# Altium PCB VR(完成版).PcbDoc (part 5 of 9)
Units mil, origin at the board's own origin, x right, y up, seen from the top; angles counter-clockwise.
Board outline 2839.68 x 2020.7 mil, 6 copper layers (TOP, GND02, SIN03, SIN04, PWR05, BOTTOM); 494 components, 404 nets, 7124 pads, 1123 vias.
Unrouted connection lines stored in the file: 10.
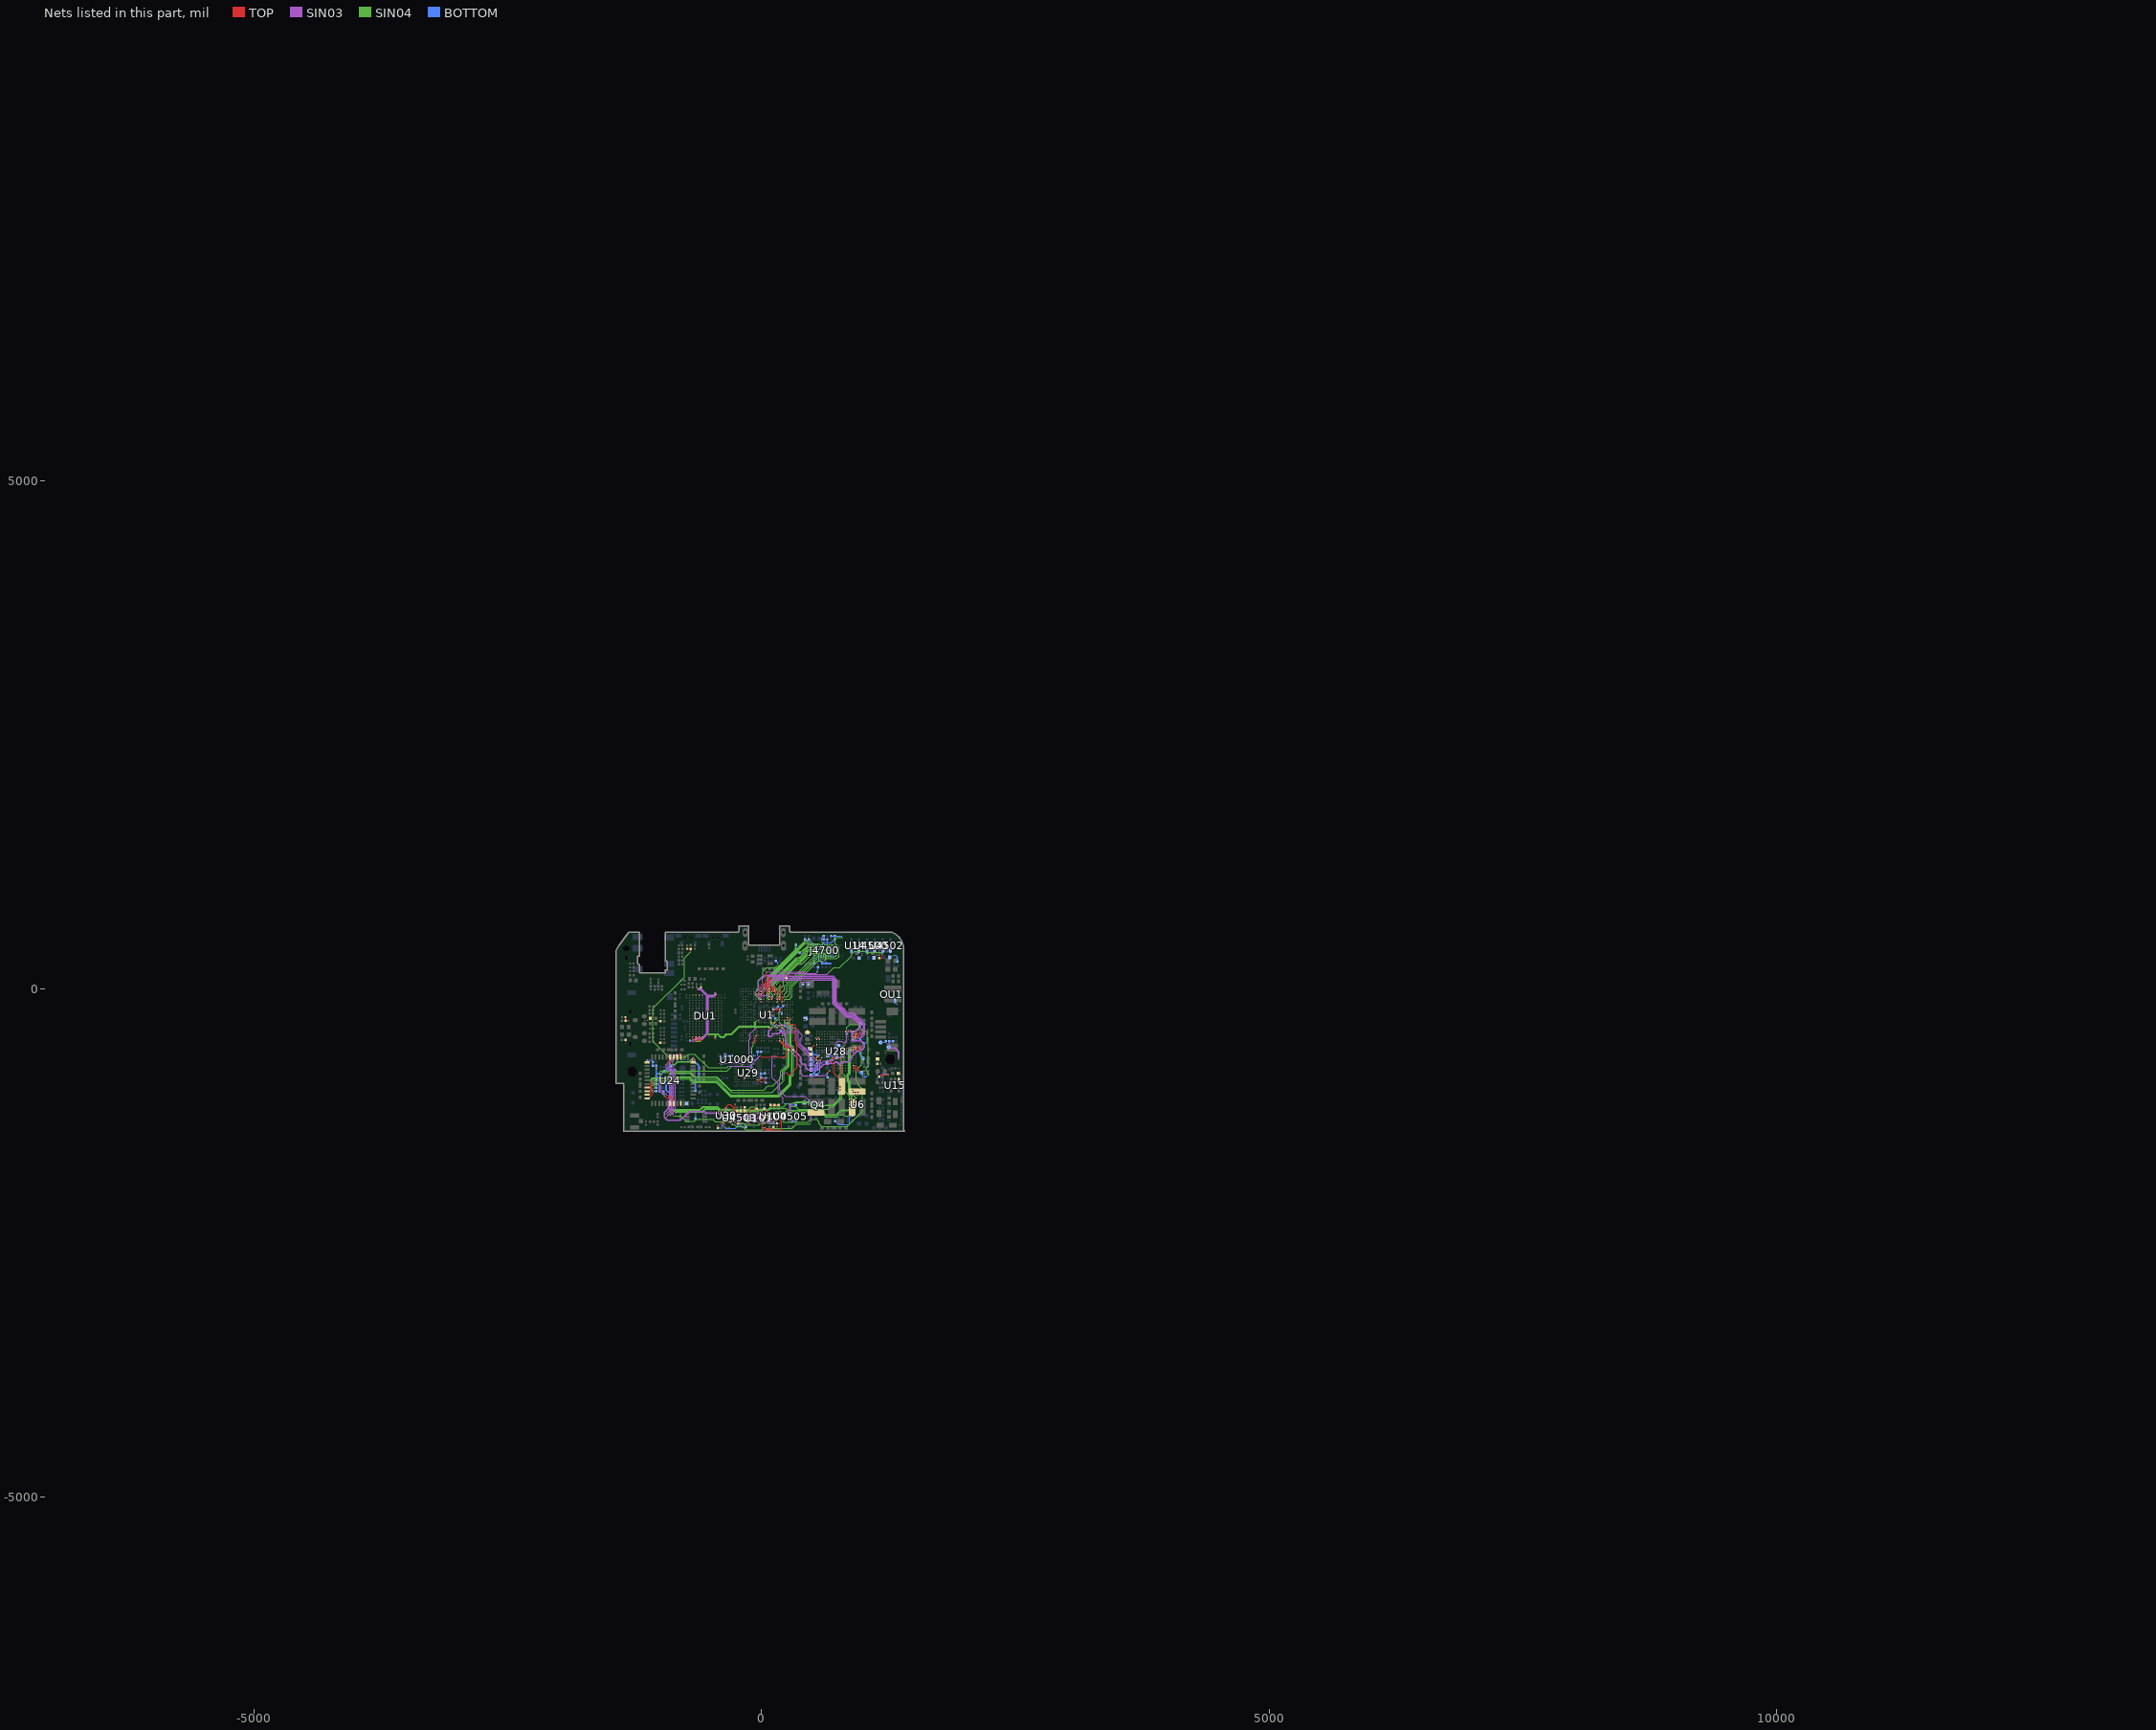
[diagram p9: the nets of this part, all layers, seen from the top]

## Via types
v1: diameter 14, hole 8, TOP to BOTTOM, tented both sides, 707 vias
v2: diameter 16, hole 10, TOP to BOTTOM, tented both sides, 275 vias
v3: diameter 16, hole 8, TOP to BOTTOM, tented both sides, 134 vias
v4: diameter 8, hole 8, TOP to BOTTOM, tented both sides, 3 vias
v5: diameter 10, hole 10, TOP to BOTTOM, tented both sides, 2 vias
v6: diameter 14, hole 8, TOP to BOTTOM, tented top, 1 vias
v7: diameter 14, hole 10, TOP to BOTTOM, tented both sides, 1 vias

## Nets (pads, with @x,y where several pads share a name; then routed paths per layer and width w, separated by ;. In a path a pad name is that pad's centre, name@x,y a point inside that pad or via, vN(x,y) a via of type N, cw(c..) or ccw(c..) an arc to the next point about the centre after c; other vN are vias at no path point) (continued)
ALDO2: C5.2 C6.2 C7.1 C76.2 C197.1 C230.2 DC1.2 DC22.2 DC23.2 DU1.A3 DU1.A4 DU1.A5 DU1.A6 DU1.A10 DU1.U3 DU1.U4 DU1.U5 DU1.U6 DU1.U10 U1.N8 U1.T12 U1.T13 U28.H2 U28.T4 | length 4187.4
  TOP w4: DU1.A6@-582.97,-58.91 DU1.A6@-580.5,-61.38
  TOP w10: -674.99,-495.43 DU1.U3@-674.99,-471.75 -674.99,-504.14 v3(-667.27,-511.86) -648.86,-511.86 -643.49,-506.49 ; DU1.U4@-643.49,-471.75 -643.49,-506.49 ; DU1.U5@-612,-471.75 -612,-501 ; DU1.U6@-580.5,-471.75 -580.5,-498.5 -583,-501 -612,-501 ; DU1.A6@-580.5,-62.3 DU1.A6@-580.5,-61.38 ; v1(-454.52,-489.45) DU1.U10@-454.52,-471.75 ; DU1.A10@-454.52,-62.3 v1@-454.52,-47.66 ; v1(-38.39,-319.89) U1.N8@-25.59,-307.09 ; U1.T12@76.77,-383.86 v1(89.57,-396.65) U1.T13@102.36,-383.86 ; U28.H2@904.95,-625.83 v3(917.75,-638.63) ; -643.49,-506.49 -617.49,-506.49 -612,-501
  TOP w12: U28.T4@853.77,-421.1 v3(866.56,-408.31)
  SIN03 w12: v1(89.57,-396.65) 71,-415.22 71,-463 77,-469 94,-469 120,-443 171,-443 186,-428 200,-428 237,-465 237,-525 386,-674 386,-722 405.81,-741.81 425.81,-741.81 439,-755 439,-775 463,-799 557,-799 613,-743 659,-743 670,-732 717,-732 732,-717 740,-717 765,-742 777,-742 801,-718 854,-718 887,-685 887,-669.37 v3(917.75,-638.63) 952.37,-604 985,-604 1014,-575 1014,-547 980,-513 898,-513 890,-505 890,-431.74 v3(866.56,-408.31)
  SIN03 w25: v3(-667.27,-511.86) -643.64,-488.22 -582.78,-488.22 -533.08,-438.53 -533.08,-71 -470,-71 -453.88,-54.88 v1(-453.88,-43.41) ; v3(-617.59,-3.54) -596.06,-3.54 -533.08,-66.53
  SIN04 w15: -62,-371 -62,-330 -51.89,-319.89 v1(-38.39,-319.89)
  SIN04 w20: v3(-667.27,-511.86) -606.41,-511.86 -544.08,-449.53 -454.52,-449.53 ; v1(-454.52,-489.45) -454.52,-449.53 ; v1@88.5,-390.5 69,-371 -62,-371 -218,-371 -295.53,-448.53 -344.58,-448.53 -373.08,-477.03 -396.58,-477.03 -424.08,-449.53 -454.52,-449.53
  BOTTOM w5: v3(866.56,-408.31) v3@874.18,-408.31 ; C230.2@890.28,-424.41 C230.2@890.41,-424.41
  BOTTOM w8: v3(917.75,-638.63) 935.52,-620.86 962.96,-620.86 C197.1@975.96,-633.86
  BOTTOM w10: DC1.2@-704.3,-510.42 -702.86,-511.86 v3(-667.27,-511.86)
  BOTTOM w12: C5.2@68,-458 C7.1@68,-418 68.22,-418 v1(89.57,-396.65) ; C230.2@890.41,-424.41 888.41,-424.41 887,-423 923,-423 971,-375 971,-347.65 C76.2@977.41,-341.24 ; C197.1@975.96,-633.86 975.96,-657.96 C6.2@1003,-685
  BOTTOM w15: v3(-667.27,-511.86) -632.63,-511.86 DC22.2@-631.19,-510.42 ; v3@874.18,-408.31 C230.2@890.28,-424.41
ALDO3: C11.2 C78.2 C227.2 R162.2 U1.T15 U28.C2 U28.T5 | length 2484
  TOP w5: 917.75,-766.58 917.75,-786.75 923.16,-792.16 951.73,-792.16
  TOP w5.5: 917.75,-766.58 941.58,-766.58 951.73,-776.73
  TOP w10: U1.T15@153.54,-383.86 v1(166.33,-396.66) ; U28.T5@828.18,-421.1 v3(840.98,-408.31) ; U28.C2@904.95,-753.78 917.75,-766.58
  TOP w15: v3(951.73,-823) 951.73,-776.73
  SIN03 w10: v1(166.33,-396.66) 195.66,-396.66 229,-430 330,-430 344,-444 344,-544 469,-669 469,-757 486,-774 548,-774 614,-708 701,-708 732,-677 732,-536 754,-514 792,-514 807,-529 826,-529 840.98,-514.02 v3(840.98,-408.31)
  SIN04 w10: v3(840.98,-408.31) 840.98,-380.02 872,-349 960,-349 971.31,-360.31 971.31,-386.31 997,-412 1026,-412 1041,-427 1041,-468 1053,-480 1053,-759.73 1033,-779.73 1033,-806.5 1053,-826.5 1053,-857.5 1044.5,-866 v1@1045,-866
  BOTTOM w5: C78.2@985,-820.06 C78.2@986.94,-822
  BOTTOM w10: v1(166.33,-396.66) 178.66,-396.66 C11.2@192,-410 ; C227.2@840.98,-443.34 v3(840.98,-408.31) ; v3(951.73,-823) 954.67,-820.06 C78.2@985,-820.06 ; C78.2@986.94,-822 986.94,-847.94 1004,-865 ; R162.2@1006.79,-532.86 1028.14,-532.86 1041,-520 v1@1041,-468
  BOTTOM w12: 1004,-865 v1(1045,-865)
  other v1: 1043,-468
AP-CK32K1: R188.1 R196.1 R464.1 | length 70.8
  BOTTOM w5: R464.1@-888.27,-832.48 R188.1@-888.27,-796.86 -853.65,-796.86 R196.1@-853.27,-797.24
AP-CK32KO: R464.2 R465.2 U28.C7 | length 2755.4
  TOP w5: U28.C7@777,-753.78 789.8,-766.58 v3(789.8,-861.93)
  SIN03 w4: v1(-944,-855) -902,-897 -902,-1199 v1(-935,-1232)
  SIN04 w4: v1@-935,-1233 -888,-1186 -788,-1186 ; -804,-1186 -788,-1186 ; v3(789.8,-861.93) 813,-885.14 813,-1027 793,-1047 793,-1080 709.84,-1163.16 680.84,-1163.16 660,-1184 362,-1184 334,-1156 295,-1156 267,-1128 250,-1128 217,-1161 91,-1161 68,-1184 -32,-1184 -52,-1164 -103,-1164 -123,-1184 -402,-1184 -430,-1156 -574,-1156 -604,-1186 -788,-1186
  BOTTOM w5: v1(-944,-855) -931.14,-867.86 R464.2@-888.27,-867.86 ; R464.2@-894.13,-862 R464.2@-888.27,-867.86 ; R465.2@-853.27,-867.86 R464.2@-888.27,-867.86
AP-CSI-SCK: J4700.6 R4700.2 U1.C12 | length 836.8
  TOP w5: v1(45,80) 45,11 64,-8 64,-38.42 U1.C12@76.77,-51.19
  SIN04 w4: v1(45,80) 45,85 436,476 479,476 v1@494,461
  BOTTOM w5: R4700.2@468.73,486.14 v1(493.87,461) 505.51,449.36 J4700.6@505.51,431.14
AP-CSI-SDA: J4700.4 R4701.2 U1.B13 | length 764.1
  TOP w5: v1(91,105.39) 91,34 116,9 116,-11.95 U1.B13@102.36,-25.59
  SIN04 w4: v1(91,105.39) 91,118 430,457 v1(471,457)
  BOTTOM w5: R4701.2@429.37,486.14 452.37,463.14 464.86,463.14 481.89,446.11 J4700.4@481.89,431.14
AP-I2S-BCLK: U1.A10 U28.R2 | length 1779.7
  TOP w5: v1(12.79,63.99) 25.59,51.19 U1.A10@25.59,0 ; U28.R2@904.95,-446.69 917.75,-433.89 937,-433.89 941,-429.89 v1(951.34,-429.89)
  SIN03 w4: v1(12.79,63.99) 12.79,99.79 40,127 503,127 ; 520,127 503,127 ; v1(951.34,-429.89) 929,-452.23 929,-468 947,-486 982,-486 1019,-449 1019,-346 913,-240 855,-240 741,-126 741,92 706,127 503,127
AP-I2S-DIN: U1.B9 U28.P2 | length 1687.5
  TOP w4: -12.8,-12.8 U1.B9@0,-25.59
  TOP w5: -12.8,-12.8 v1(-12.8,38.39) ; U28.P2@904.95,-472.28 917.75,-459.48 v3(943.34,-459.48)
  SIN03 w4: v1(-12.8,38.39) 28.39,38.39 65,75 65,109 75,119 699,119 731.87,86.13 731.87,-132.87 847,-248 905,-248 1011,-354 1011,-439 976,-474 957.85,-474 v3(943.34,-459.48)
AP-I2S-DOUT0: U1.E9 U28.P1 | length 1689.3
  TOP w4: -12.8,-89.57 U1.E9@0,-102.37
  TOP w5: -12.8,-89.57 v1(-12.8,-38.39) ; U28.P1@930.54,-472.28 933.26,-475 953.41,-475 v3(968.93,-459.48)
  SIN03 w4: v1(-12.8,-38.39) -12.8,2.2 5,20 34,20 122,108 478,108 ; 515,108 478,108 ; v3(968.93,-459.48) 1003,-425.41 1003,-358 905,-260 846,-260 722.68,-136.68 722.68,82.32 697,108 478,108
AP-I2S-LRCK: U1.C9 U28.R1 | length 1502.9
  TOP w5: U1.C9@0,-51.19 12.8,-38.39 v1(12.8,-12.79) ; U28.R1@930.54,-446.69 932.23,-445 961.82,-445 v1@976.93,-429.89
  SIN03 w4: v1(12.8,-12.79) 35.59,10 45,10 134,99 693,99 713.49,78.51 713.49,-140.49 842,-269 898,-269 976.93,-347.93 v1@976.93,-429.89
  other v1: 973.93,-429.89
AP-I2S-MCLK: U1.C8 U28.T2 | length 1535.3
  TOP w4: v1(-38.39,-38.39) U1.C8@-25.59,-51.19
  TOP w5: U28.T2@904.95,-421.1 917.75,-408.31 v1(963.93,-408.31)
  SIN03 w4: v1(-38.39,-38.39) -20.78,-56 -3,-56 141,88 373,88 394,67 492,67 513,88 583,88 688,88 705,71 705,-144 840,-279 894,-279 963.93,-348.93 v1(963.93,-408.31)
AP-NMI#: C280.2 R33.2 U1.Y16 U28.A11 | length 975.4
  TOP w4: U1.Y16@179.13,-486.23 v1(191.93,-499.02)
  TOP w5: v1(191.93,-499.02) 191.93,-510.93 255,-574 288,-574 C280.2@314,-600 ; v3(661.83,-817.76) U28.A11@674.63,-804.96
  SIN03 w4: v1(191.93,-499.02) 191.93,-519.93 355.5,-683.5 355.5,-741.5 386,-772 386,-834 406,-854 625.59,-854 v3(661.83,-817.76)
  BOTTOM w5: R33.2@650.41,-866.86 650.41,-829.18 v3(661.83,-817.76)
AP-RESET#: C79.2 C277.1 R17.2 R93.1 R1006.1 U1.AA16 | length 3580.4
  TOP w4: U1.AA16@179.13,-511.82 191.93,-524.61
  TOP w5: v1(-15,-659) 0,-674 85,-674 98,-661 v1(145,-661) 156,-672 230,-672 246,-656 246,-621 C277.1@268,-599 266.32,-599 191.93,-524.61
  TOP w10: C79.2@-730.27,396.69 -696.82,396.69 R17.2@-694.27,394.14 v1(-694.27,366.14)
  SIN03 w4: v1(-323,-760) -116,-760 v1(-15,-659) ; v1(145,-661) 116,-661 105,-672 105,-874 167,-936 167,-1028 214,-1075 v2(214,-1130)
  SIN04 w4: v1(-694.27,366.14) -759,301.41 -759,116 -1068,-193 -1068,-515 -913,-670 -746.89,-670 -718.89,-642 -656.11,-642 -523.11,-775 -338,-775 v1(-323,-760)
  BOTTOM w5: R1006.1@-86.89,-693.25 -49.25,-693.25 v1(-15,-659) ; v2(214,-1130) 284,-1130 297.24,-1143.24 317,-1143.24 ; 310.11,-1143.24 317,-1143.24 ; R93.1@340.41,-1143.24 317,-1143.24
AP-UART1-CTS: R179.2 U1.N19 U24.41 | length 2292.6
  TOP w4: v1(243.1,-319.89) U1.N19@255.9,-307.09
  TOP w5: U24.41@-1126.27,-971.56 -1108.56,-971.56 -1089,-952 -1089,-926 v2(-1064,-901)
  SIN04 w4: v2(-1064,-901) -931,-901 -904,-874 -711,-874 -674,-911 -444,-911 -302.5,-1052.5 170.5,-1052.5 285,-938 285,-862 305,-842 305,-575 283,-553 283,-422 292,-413 292,-368.78 v1(243.1,-319.89)
  BOTTOM w5: v2(-1064,-901) -1037.39,-901 R179.2@-1037.27,-901.12
AP-UART1-RTS: R182.2 U1.N18 U24.44 | length 2479
  TOP w4: v1(217.51,-319.89) U1.N18@230.31,-307.09
  TOP w5: U24.44@-1126.27,-1077.86 -1109.86,-1077.86 -1066,-1034 v2(-1066,-1008)
  SIN04 w4: v2(-1066,-1008) -1085,-989 -1085,-959 -1078,-952 -1053,-952 -1047.65,-946.65 -1047.65,-929.35 -1060,-917 -1073,-917 -1080,-910 -1080,-893 -1073,-886 -929,-886 -906,-863 -706,-863 -669,-900 -442,-900 -299.92,-1042.08 167.92,-1042.08 273,-937 273,-858 296,-835 296,-585 272,-561 272,-419 282,-409 282,-374 245.19,-337.19 234.81,-337.19 v1(217.51,-319.89)
  BOTTOM w5: v2@-1063,-1008 -1037.41,-1008 R182.2@-1037.27,-1007.86
AP-UART1-RX: R180.2 U1.N16 U24.42 | length 2350.1
  TOP w4: v1(166.33,-319.89) U1.N16@179.13,-307.09
  TOP w5: U24.42@-1126.27,-1006.99 -1109.99,-1006.99 -1089,-986 -1089,-969 -1076,-956 -1076,-947 v2(-1066,-937) -1066,-940 v2@-1063,-937
  SIN04 w4: v2(-1066,-937) -1088,-915 -1088,-888 -1075,-875 -937,-875 -894,-832 -702,-832 -654.5,-879.5 -435.5,-879.5 -293,-1022 107,-1022 224,-905 224,-813 276,-761 276,-599 251,-574 251,-412 260,-403 260,-389 227,-356 202.45,-356 v1(166.33,-319.89)
  BOTTOM w5: v2@-1063,-937 -1037.57,-937 R180.2@-1037.27,-936.7
AP-UART1-TX: R181.2 U1.M19 U24.43 | length 2384
  TOP w4: U1.M19@255.9,-281.5 268.7,-294.3
  TOP w5: U24.43@-1126.27,-1042.42 -1111.42,-1042.42 -1088,-1019 -1088,-1006 -1076,-994 -1076,-985 v2@-1064,-973 ; 268.7,-294.3 v1(294.29,-294.3)
  SIN04 w4: v2(-1066,-973) -1055,-973 -994,-912 -920,-912 -896,-888 -715,-888 -682,-921 -446,-921 -304.08,-1062.92 175.08,-1062.92 295,-943 295,-869 316,-848 316,-570 295,-549 295,-422 305.5,-411.5 305.5,-365.5 275,-335 275,-313.59 v1(294.29,-294.3)
  BOTTOM w5: v2@-1064,-973 -1037.99,-973 R181.2@-1037.27,-972.28
AP-WAKE-BT: R193.2 U1.W7 U24.6 | length 1619.8
  TOP w4: -63.98,-473.42 U1.W7@-51.18,-460.63
  TOP w5: v2(-956.27,-1052.86) -938.27,-1070.86 -914.14,-1070.86 -898.92,-1086.08 U24.6@-898.92,-1128.05 ; v1(-89.57,-524.61) -68.61,-524.61 -63.98,-519.98 -63.98,-473.42
  SIN03 w4: v1(-1004,-856) -1004,-1005.13 v2(-956.27,-1052.86)
  SIN04 w4: v1(-1004,-856) -1004,-827 -987,-810 -340,-810 -290.3,-760.3 -202.3,-760.3 -94,-652 -94,-576 -77,-559 -77,-537.18 v1(-89.57,-524.61)
  BOTTOM w5: R193.2@-965,-1009.69 -965,-1031.86 -956.27,-1040.59 v2(-956.27,-1052.86)
AS-INT: R482.2 U1.P19 U30.12 | length 2407.9
  TOP w5: U30.12@-305.9,-1307.92 -305.9,-1315.23 v2(-287.27,-1333.86) ; v2(28.73,-1358.86) 47.87,-1378 100.96,-1378 R482.2@120.73,-1358.24 ; v1(246,-827) 263,-844 283,-844 352,-775 352,-535 334,-517 334,-363 316,-345 268.22,-345 U1.P19@255.9,-332.68
  SIN03 w4: v1(246,-827) 224,-827 179,-872 179,-999 239,-1059 429,-1059 491,-1121 v1(491,-1318)
  SIN04 w4: v2(-287.27,-1333.86) -267.14,-1333.86 -248.3,-1352.7 -186.3,-1352.7 -152,-1387 0.59,-1387 v2(28.73,-1358.86) 44.87,-1375 301,-1375 343,-1333 476,-1333 v1(491,-1318)
AUX_CL: R521.1 U30.7 | length 469.2
  TOP w5: v2(-399.27,-1329.86) -384.64,-1315.23 U30.7@-384.64,-1307.92 ; R521.1@-126.89,-1246.86 -126.89,-1245.89 v1(-106,-1225)
  BOTTOM w5: v2(-399.27,-1329.86) -353.13,-1376 -256,-1376 -235,-1355 -235,-1294 -220,-1279 -160,-1279 v1(-106,-1225)
AUX_DA: R522.1 U30.21 | length 384.5
  TOP w5: U30.21@-337.4,-1189.8 -337.4,-1151.99 -322.41,-1137 -306,-1137 -274,-1169 -274,-1194 -260,-1208 -260,-1219 -252,-1227 v2(-252,-1243) ; R522.1@-126.89,-1284.86 -120,-1291.75 v1(-120,-1305)
  SIN03 w4: v2(-252,-1243) -213,-1282 -161,-1282 -138,-1305 v1(-120,-1305)
AVDD-CSI: C275.1 U28.E10 | length 108.1
  TOP w8: U28.E10@700.23,-702.6 717,-685.83 717,-668.19 v3(713.03,-664.22)
  BOTTOM w12: C275.1@653.41,-656.24 657.03,-659.86 v3@713.03,-659.86
BACK: R135.2 TP74.1 | length 56.4
  BOTTOM w5: TP74.1@1173.73,-527.86 1211.73,-527.86 R135.2@1224.73,-514.86
BB-VBAT: C234.2 C264.1 C268.2 C269.2 L11.2 Q4.1 Q4.2 Q4.5 Q4.6 Q4.8 R319.2 U24.9 U28.L16 | length 56.6
  TOP w5: C268.2@486.73,-590.86 486.73,-584.86 522.53,-549.05
  other v1: 420,-1162 438,-1162 420,-1139 438,-1139 420,-1090.86 436,-1090.86
  other v2: -803.27,-1152.86 -783.27,-1152.86
BMG160-SCK: R518.2 R520.2 R521.2 R5134.1 U101.7 U4503.B3 | length 807
  TOP w5: U4503.B3@-197.47,-1269.06 -184.47,-1269.06 R521.2@-162.27,-1246.86 -95.27,-1179.86 v1(-76,-1179.86) R518.2@-45.27,-1179.86 -45.27,-1237.73 -27.27,-1255.73 -14.27,-1255.73 -5.27,-1264.73 -5.27,-1304.86 2.1,-1312.23 U101.7@20.03,-1312.23 20.03,-1332.97 13,-1340 13,-1374 28,-1389 188,-1389 201,-1376 201,-1302 172.86,-1273.86 v1(172.86,-1262.86)
  BOTTOM w5: v1(-76,-1179.86) R520.2@-45.27,-1179.86 ; v1(172.86,-1262.86) R5134.1@193.35,-1262.86
BMG160SDA: R517.2 R519.2 R522.2 R5135.1 U101.9 U4503.C3 | length 784.2
  TOP w5: U4503.C3@-197.47,-1284.86 R522.2@-162.27,-1284.86 -122.13,-1325 v1(-106,-1325) ; U101.9@20.03,-1272.86 34.73,-1272.86 46.73,-1260.86 46.73,-1224.86 v2(56.73,-1214.86) 45.73,-1203.86 45.73,-1196.86 29.73,-1180.86 R517.2@29.73,-1179.86
  BOTTOM w5: v1(-106,-1325) -127,-1325 -135,-1317 -135,-1279 -77,-1221 -29,-1221 12.14,-1179.86 R519.2@29.73,-1179.86 44.86,-1179.86 56.23,-1191.23 56.23,-1214.36 39,-1231.59 39,-1250 51,-1262 70,-1262 103,-1229 192.21,-1229 R5135.1@194.35,-1226.86
BT-PCM-CLK: U24.26 U28.K2 | length 3363.3
  TOP w5: U24.26@-828.05,-673.33 v2@-828.05,-633.19 ; U28.K2@904.95,-574.65 v3(917.75,-561.85)
  SIN03 w4: v1(-904,-1252) -879,-1227 -879,-816 -916,-779 -916,-720.7 v2(-828.27,-632.97)
  SIN04 w4: v1@-903,-1252 -856,-1205 -582,-1205 -552,-1175 -435,-1175 -407,-1203 -28.27,-1203 26.73,-1258 73.27,-1258 86.14,-1245.14 86.14,-1229.86 98,-1218 126,-1218 142,-1202 196,-1202 212,-1218 229.27,-1218 246.27,-1201 586,-1201 632,-1247 743,-1247 792,-1198 885,-1198 894.14,-1188.86 894.14,-1047.86 867,-1020.73 867,-917 852,-902 852,-849 867,-834 867,-612.6 v3(917.75,-561.85)
BT-PCM-DIN: U24.27 U28.K1 | length 3207.5
  TOP w5: v2(-872.27,-716.86) -863.48,-708.07 U24.27@-863.48,-673.33 ; U28.K1@930.54,-574.65 v3(943.34,-561.85)
  SIN03 w4: v2(-872.27,-716.86) -872.27,-780.73 -849,-804 v1(-849,-1226)
  SIN04 w4: v1(-849,-1226) -837,-1214 -578.27,-1214 -548.27,-1184 -439,-1184 -412,-1211 -33,-1211 23,-1267 77,-1267 96.21,-1247.79 96.21,-1232.79 102,-1227 135,-1227 150,-1212 192,-1212 207,-1227 233,-1227 250,-1210 582,-1210 631,-1259 751,-1259 767,-1243 813,-1243 823.53,-1253.53 858.47,-1253.53 935,-1177 935,-1076 876,-1017 876,-911 861,-896 861,-852 876,-837 876,-629.19 v3(943.34,-561.85)
BT-PCM-DOUT: U24.25 U28.J1 | length 3561.4
  TOP w5: U24.25@-792.62,-673.33 v2@-792.62,-633.62 ; U28.J1@930.54,-600.24 956.13,-600.24 v3(994.52,-561.85)
  SIN03 w4: v1(-864,-1251) -864,-811 -903,-772 -903,-724 -832.44,-653.44 -812.74,-653.44 v2(-792.27,-632.97)
  SIN04 w4: v1(-864,-1251) -795,-1251 -741.62,-1304.38 -658.38,-1304.38 -640,-1286 -480,-1286 -456,-1310 -243,-1310 -229,-1324 -184,-1324 -165,-1343 -20,-1343 -1,-1324 115,-1324 153,-1286 191,-1286 216,-1311 460,-1311 485,-1286 544,-1286 565.1,-1307.09 565.1,-1326.09 593,-1354 843,-1354 994,-1203 994,-988 958,-952 958,-931 932,-905 932,-798 984.15,-745.85 984.15,-572.22 v3(994.52,-561.85)
BT-PCM-SYNC: U24.28 U28.J3 | length 3267.3
  TOP w5: v2(-934.27,-741.86) -898.92,-706.5 U24.28@-898.92,-673.33 ; U28.J3@879.36,-600.24 892.16,-587.44 v3(892.16,-561.85)
  SIN03 w4: v2(-934.27,-741.86) -934.27,-778.73 -891,-822 -891,-1212 v1(-934,-1255)
  SIN04 w4: v1(-934,-1255) -874,-1195 -793,-1195 ; -804,-1195 -793,-1195 ; v3(892.16,-561.85) 857,-597.01 857,-827 844,-840 844,-907 857,-920 857,-1024.87 885,-1052.87 885,-1180 876,-1189 785,-1189 736,-1238 636,-1238 591,-1193 262,-1193 244,-1175 92,-1175 74,-1193 -405,-1193 -433,-1165 -570.27,-1165 -600.27,-1195 -793,-1195
BT-RST-N: R190.1 R194.2 U24.34 | length 126.4
  TOP w5: v2@-1129.27,-698.86 v2(-1126.27,-701.86) U24.34@-1126.27,-723.52
  BOTTOM w5: v2(-1126.27,-701.86) -1087.27,-701.86 R194.2@-1070.27,-718.86 -1069.27,-719.86 R190.1@-1069.27,-755.86
BT-WAKE-AP: U1.W17 U24.7 | length 2120.4
  TOP w4: U1.W17@204.72,-460.63 v1(217.52,-473.42)
  TOP w5: v2(-924.27,-1053.86) -897.14,-1053.86 -863.48,-1087.52 U24.7@-863.48,-1128.05
  SIN03 w4: v1(-982.07,-857.07) -982.07,-996.06 v2(-924.27,-1053.86)
  SIN04 w4: v1(-982.07,-857.07) -982.07,-832.07 -971,-821 -694,-821 -650,-865 -437,-865 -307,-995 24,-995 64.19,-954.81 116.68,-954.81 191,-880.49 191,-808 249,-750 249,-611.48 217.52,-580 v1(217.52,-473.42)
CAD: R490.1 R491.1 U4503.A2 | length 93.2
  TOP w5: U4503.A2@-213.27,-1253.36 -213.27,-1238.86 -202.55,-1228.14 R491.1@-202.55,-1201.86 R490.1@-165.27,-1201.86
CIF_CLKI: C4700.2 R4702.2 U1.E15 | length 1213.1
  TOP w4: U1.E15@153.54,-102.37 166.33,-89.57
  TOP w5: 166.33,-89.57 v1(191.92,-89.57)
  SIN04 w4: v1(191.92,-89.57) 203.49,-78 252,-78 278,-52 278,21 555,298 743,298 764,319 764,409 727,446 727,489 743,505 v1(800,505)
  BOTTOM w5: C4700.2@687.06,519.97 688.61,521.52 R4702.2@723.48,521.52 783.48,521.52 v1(800,505)
CIF_CLKIN: J4700.18 R4702.1 | length 106.9
  BOTTOM w5: J4700.18@647.24,431.14 647.24,444.65 655.73,453.14 690.48,453.14 R4702.1@723.48,486.14
CIF_CLKO: R4703.2 U1.E16 | length 1097.3
  TOP w5: U1.E16@179.13,-102.37 181.76,-105 202.08,-105 217.51,-89.57 v1(217.51,-63.98)
  SIN04 w4: v1(217.51,-63.98) 252,-29.5 252,22 547,317 725,317 744,336 744,396 703,437 622,437 v1(594,465)
  BOTTOM w5: v1(594,465) 594,501.29 R4703.2@614.23,521.52
CIF_CLKOUT: C4701.2 J4700.14 R4703.1 | length 133.3
  BOTTOM w5: J4700.14@600,431.14 600,446.41 610.73,457.14 642.73,457.14 650.64,465.06 C4701.2@650.64,487.69 649.1,486.14 R4703.1@614.23,486.14
CIF_D0: J4700.20 U1.D15 | length 825.6
  TOP w4: U1.D15@153.54,-76.78 v1(166.33,-63.98)
  SIN04 w4: v1(166.33,-63.98) 166.33,-32.67 181,-18 181,-4 220,35 220,103 366.07,249.07 404.07,249.07 499,344 637.59,344 v1(659.59,366)
  BOTTOM w5: v1(659.59,366) 659.59,415.59 670.86,426.86 J4700.20@670.86,431.14
CIF_D1: J4700.22 U1.F15 | length 879.8
  TOP w4: U1.F15@153.54,-127.96 v1(166.33,-115.16)
  SIN04 w4: v1(166.33,-115.16) 166.33,-85.67 182,-70 182,-52 226,-8 226,24 538,336 681,336 710,365 710,390.38 v1(694.48,405.9)
  BOTTOM w5: v1(694.48,405.9) J4700.22@694.48,431.14
CIF_D2: J4700.23 U1.E13 | length 1024.5
  TOP w4: U1.E13@102.36,-102.37 v1(115.16,-89.57)
  SIN04 w4: v1(115.16,-89.57) 115.16,-66.16 86,-37 86,52 343,309 374,309 418.18,353.18 418.18,375.18 465,422 556,422 597,381 690.63,381 v1(694.48,377.14)
  BOTTOM w5: v1(694.48,377.14) 706.29,365.33 J4700.23@706.29,322.48
CIF_D3: J4700.21 U1.D13 | length 1051.9
  TOP w4: v1(89.57,-89.58) U1.D13@102.36,-76.78
  SIN04 w4: v1(89.57,-89.58) 71,-71.01 71,53 123,105 123,123 370,370 398,370 461,433 557,433 599,391 657,391 v1(673,407) v1@672,407
  BOTTOM w5: v1(673,407) 673,370 682.67,360.33 J4700.21@682.67,322.48
CIF_D4: J4700.19 U1.B14 | length 754.1
  TOP w5: U1.B14@125.95,-25.59 125.95,23.58 v1(140.75,38.38)
  SIN04 w4: v1(140.75,38.38) 363.37,261 388,261 465,338 478,338 493,353 622.97,353 v1(635.97,366)
  BOTTOM w5: v1(635.97,366) 659.05,342.92 J4700.19@659.05,322.48
CIF_D5: J4700.17 U1.F17 | length 690.5
  TOP w4: U1.F17@204.72,-127.96 v1(217.52,-115.16)
  SIN04 w4: v1(217.52,-115.16) 232.68,-100 278,-100 300,-78 300,16 558,274 v1(618,274)
  BOTTOM w5: v1(618,274) 635.43,291.43 J4700.17@635.43,322.48
CIF_D6: J4700.15 U1.C14 | length 789.1
  TOP w4: U1.C14@127.95,-51.19 140.75,-38.39
  TOP w5: 140.75,-38.39 v1(140.75,12.79)
  SIN04 w4: v1(140.75,12.79) 124,29.54 124,43 353,272 382,272 451.37,341.37 451.37,364.37 462,375 521,375 531,365 v1@606,365
  BOTTOM w5: v1(607,366) 607,345.81 611.81,341 J4700.15@611.81,322.48
CIF_D7: J4700.13 U1.E12 | length 1047
  TOP w4: v1(63.98,-115.17) U1.E12@76.77,-102.37
  SIN04 w4: v1(63.98,-115.17) 63.98,-87.98 58,-82 58,53 110,105 110,124 429,443 566,443 v1(602,407)
  BOTTOM w5: 585,405 576.66,396.66 ; J4700.13@588.18,322.48 588.18,347.63 569,366.81 569,389 576.66,396.66 ; v1(602,407) 587,407 576.66,396.66
CIF_DVDD: C4704.2 J4700.11 R4705.2 R4706.2 | length 165
  BOTTOM w10: 564.56,289.31 J4700.11@564.56,322.48
  BOTTOM w15: 564.56,289.31 598.93,254.94 R4706.2@598.93,251.19 600.48,249.64 C4704.2@677.73,249.64
CIF_HREF: J4700.10 U1.D16 | length 881.4
  TOP w5: v1(179,38) 191.92,25.08 191.92,-63.98
  TOP w5.5: U1.D16@179.13,-76.78 191.92,-63.98
  SIN04 w4: v1(179,38) 179,19 159,-1 135,-1 113,21 113,47 352,286 382,286 438,342 438,366 462,390 536.59,390 v1(552.75,406.17)
  BOTTOM w5: v1(552.75,406.17) J4700.10@552.75,431.14
CIF_PDN0: R5118.1 U1.B12 | length 780.7
  TOP w5: v1(49,166) 49,130 75,104 75,25 90,10 90,-12.36 U1.B12@76.77,-25.59
  SIN03 w4: v1(49,166) 431,166 444,153 539,153 v1(552,166)
  BOTTOM w5: v1(552,166) 552,185.47 559.53,193 R5118.1@559.53,215.81
CIF_PDN1: R4707.2 R4708.2 R5117.1 U1.A12 | length 703.1
  TOP w5: v1(46,105) 60,91 60,16.77 U1.A12@76.77,0
  SIN04 w4: v1@47,104 51,104 340.73,393.73 v1(340.73,461.14)
  BOTTOM w5: R4707.2@340.73,356.98 R4708.2@340.73,393.98 R5117.1@340.73,430.98 v1(340.73,461.14)
CIF_RST: C4705.2 J4700.7 R4704.1 | length 112.2
  BOTTOM w5: C4705.2@480.73,249.64 480.73,251.19 R4704.1@517.32,251.19 ; J4700.7@517.32,322.48 R4704.1@517.32,251.19 ; R4704.1@520.13,251.19 R4704.1@517.32,251.19
CIF_VSYNC: J4700.8 U1.C15 | length 763.7
  TOP w4: U1.C15@153.54,-51.19 166.33,-38.39
  TOP w5: 166.33,-38.39 v1(166.34,-12.8)
  SIN04 w4: v1(166.34,-12.8) 128.8,-12.8 103,13 103,52 349,298 377,298 428,349 428,371 462.14,405.14 v1(521.73,405.14)
  BOTTOM w5: v1(521.73,405.14) 529.13,412.54 J4700.8@529.13,431.14
DC1-SW: C117.2 C119.2 C135.2 C216.1 C273.1 L4.1 R86.2 R127.1 U6.4 U6.5 U15.1 U28.J5 | length 1217.2
  TOP w5: R127.1@1159.35,-865.61 1180.1,-844.86 v2(1247.73,-844.86)
  TOP w10: U28.J5@828.18,-600.24 v3(840.98,-613.04)
  SIN03 w0: 1265,-582 1313,-582
  SIN03 w20: 1202.73,-844.86 v2(1247.73,-844.86) ; 1313,-582 1349.73,-618.73 v2(1349.73,-687.86)
  SIN04 w10: v3(840.98,-613.04) 815.39,-638.63 815.39,-716.61 796,-736 796,-830.61 825,-859.61 825,-1013 867.73,-1055.73 v2(867.73,-1155.86)
  BOTTOM w10: R86.2@726.01,-1305.24 757.78,-1337 857,-1337 869,-1325 869,-1265 891.14,-1242.86 C135.2@896.41,-1242.86 ; v3(840.98,-613.04) 854.49,-613.04 C273.1@872.67,-594.86
  other v1: 1220,-636
  other v2: 915.73,-1131.86 867.73,-1130.86 867.73,-1104.86
  other v4: 1220,-610
DCDC1: C12.2 C21.2 C22.2 C53.2 C82.1 C98.2 C99.2 C100.2 C101.2 C179.2 C180.2 C185.2 C186.2 C191.2 C199.1 C203.2 C228.2 C272.1 C289.1 C290.2 C291.2 C326.2 C341.1 C4500.1 C4505.1 C4718.2 ED30.1 L1.2 OU1.4 R6.2 R7.2 R18.2 R24.1 R27.1 R29.1 R121.1 R122.1 R123.1 R126.1 R128.2 R129.1 R136.2 R167.2 R329.2 R481.2 R485.2 R489.2 R490.2 R497.2 R498.2 R1007.2 R1010.1 R4707.1 R5123.1 R5124.1 R5136.1 U1.F9 U1.L13 U1.R16 U1.T7 U14.1 U28.F16 U28.J6 U28.K6 U28.N2 U29.AA3 U29.AA5 U29.K6 U29.M6 U29.N5 U29.T10 U29.U9 U29.W4 U29.Y4 U30.8 U30.13 U30.22 U100.3 U100.7 U101.2 U101.10 U1000.6 U4500.1 U4502.1 U4503.A1 U4503.C1 U4505.8 | length 4879.4
  TOP w5: U28.J6@802.59,-600.24 815.39,-587.44 v3(840.98,-587.44) ; U28.K6@802.59,-574.65 v3(815.39,-561.85) ; U28.N2@904.95,-497.87 v3(917.75,-485.07)
  TOP w6: U29.K6@-221.22,-857.39 v1(-202.83,-839) -199,-839 U29.M6@-181.85,-856.15 ; v3(508.3,-689.8) 533.89,-689.8 U28.F16@546.68,-677.01
  TOP w8: v2(306.73,-1271.86) 318.26,-1283.39 U4505.8@341.77,-1283.39
  TOP w10: C326.2@-1338.82,-277.86 -1338.82,-313.31 R1010.1@-1337.27,-314.86 v1(-1310.27,-314.86) ; v1(-1337.27,-528.86) R5124.1@-1337.27,-502.86 ; v1(-1018.27,-528.86) -991.65,-528.86 R123.1@-991.65,-529.25 ; v1(-1011,-316) -993.49,-316 R122.1@-991.65,-317.84 ; R167.2@-427.65,-1367.86 v2(-427.65,-1330.24) ; v2(-368.89,-1333.48) U30.8@-368.89,-1307.92 ; U30.22@-353.14,-1189.8 v2(-353.14,-1169) ; U30.13@-286.21,-1288.23 -265.9,-1288.23 -247.96,-1306.17 v2@-247.96,-1326.41 ; v1@-259,-1137 -259,-1186 -239.27,-1205.73 -239.27,-1218.86 -228.97,-1229.16 U4503.A1@-228.97,-1253.36 ; v2(-252.82,-1326.41) v2@-247.96,-1326.41 ; U4503.C1@-228.97,-1284.86 -228.97,-1325.71 C191.2@-228.27,-1326.41 v2@-247.96,-1326.41 ; v1(-202.83,-839) v1@-200.24,-839 ; U29.M6@-181.85,-857.39 U29.M6@-181.85,-856.15 ; R490.2@-165.27,-1166.48 v2(-140.65,-1166.48) ; v1(-162.17,-897.83) U29.N5@-162.17,-877.07 ; U29.T10@-103.11,-778.65 -103.11,-798.89 -102.55,-798.33 U29.U9@-83.43,-798.33 ; U101.2@-74.58,-1253.17 v2@-47.68,-1253.17 ; v1(-63.98,-396.65) U1.T7@-51.18,-383.86 ; U29.W4@-44.06,-896.76 U29.Y4@-24.37,-896.76 U29.AA5@-4.69,-877.07 24.07,-877.07 v1(45,-898) 26.56,-916.44 U29.AA3@-4.69,-916.44 ; v1(-12.8,-115.16) U1.F9@0,-127.96 ; v2(4.23,-1211.36) -2.27,-1217.86 -2.27,-1246.86 4.04,-1253.17 U101.10@20.03,-1253.17 ; U100.3@90.02,-1263.7 108.3,-1263.7 116,-1256 v2(116,-1244) ; R485.2@92.73,-1144.48 R126.1@130.73,-1144.48 R481.2@168.73,-1144.48 ; U1.L13@102.36,-255.91 v1(115.16,-268.7) ; U100.7@151.44,-1283.39 151.44,-1321.11 C179.2@154.73,-1324.41 157.18,-1326.86 v2(184.73,-1326.86) ; U1.R16@179.13,-358.27 v1(191.93,-371.06) ; R329.2@248,106.38 281.38,139.76 v1(281.38,140)
  SIN03 w10: v1(-420,-733) -184,-733 -120,-669 -120,-504 -110,-494 -110,-442.67 v1(-63.98,-396.65)
  SIN04 w10: v1(-12.8,-115.16) -12.8,-96 -22,-96 -61,-57 -61,-30 -31,0 -31,83 14,128 14,170 52,208 134.59,208 v1(159.73,233.14) ; v1(115.16,-268.7) 95,-288.86 95,-352 114.06,-371.06 v1(191.93,-371.06) 228,-407.14 228,-440 236.13,-448.13 236.13,-581 263,-607.87 263,-755 210,-808 v1(210,-899)
  BOTTOM w5: C82.1@491.2,-692.98 C82.1@494.37,-689.81
  BOTTOM w10: R5123.1@-647.58,-1278.08 -647.58,-1259.58 -643,-1255 v2(-643,-1229) ; v1(-420,-733) R498.2@-391.38,-733 -391.38,-691.5 C341.1@-357.88,-658 ; v2(-368.89,-1333.48) C290.2@-368.89,-1306.37 ; v1(-357.88,-627.12) C341.1@-357.88,-658 ; C289.1@-353.14,-1191.35 v2(-353.14,-1169) ; U1000.6@-301.24,-657.6 -357.48,-657.6 C341.1@-357.88,-658 ; C291.2@-291.27,-1304.31 -274.91,-1304.31 v2(-252.82,-1326.41) ; v2(-213,-1307) -213,-1340 -193.14,-1359.86 R489.2@-155.27,-1359.86 ; v1(-162.17,-897.83) -161,-896.66 C101.2@-161,-868 ; v1@-103.11,-798.89 -103.11,-782.56 C99.2@-93.55,-773 -93.55,-735.93 R497.2@-88.62,-731 ; R1007.2@-86.89,-657.25 v1(-47.25,-657.25) -37.75,-647.75 R7.2@-37.75,-619.86 R6.2@-2.5,-619.86 ; C185.2@-74.58,-1254.72 v2@-46.13,-1254.72 ; v1(-63.98,-396.65) -63.98,-376.98 C22.2@-60,-373 ; C12.2@-22,-92 -12.8,-101.2 v1(-12.8,-115.16) ; v2(4.23,-1211.36) 4.23,-1221.36 18.48,-1235.61 C203.2@18.48,-1253.17 ; R128.2@21.73,-1320.86 R128.2@19.73,-1318.86 75.86,-1318.86 83.86,-1326.86 v2(184.73,-1326.86) ; R24.1@36.31,-833 2.65,-833 R27.1@-1.26,-836.91 R29.1@-1.26,-874.86 -0.12,-876 C100.2@45,-876 v1(45,-898) 45,-924 C98.2@44,-925 ; v1(115.16,-268.7) 116.71,-268.7 C21.2@138,-290 ; C180.2@116,-1266.86 v2(116,-1244) ; R136.2@141.73,273.76 159.73,255.76 v1@159.73,237.14 ; R5136.1@303.73,-1298.86 C4718.2@333.73,-1298.86 ; v2(306.73,-1271.86) C4718.2@333.73,-1298.86 ; C4718.2@340.18,-1298.86 C4718.2@341.18,-1299.86 334.73,-1299.86 C4718.2@333.73,-1298.86 ; R4707.1@376.11,356.98 376.94,356.14 v1(400.73,356.14) ; C272.1@773,-559 775.85,-561.85 v3(815.39,-561.85) ; v3(917.75,-485.07) 938.53,-505.86 962.73,-505.86 C228.2@975.73,-492.86 ; 1299.73,330.14 1321.73,330.14 1339.11,312.76 R18.2@1339.11,271.71 ; OU1.4@1318.13,-116.73 1318.13,-134.26 v1(1338.73,-154.86)
  BOTTOM w12: C82.1@494.37,-689.81 v3(508.3,-689.8)
  other v1: -259,-1135.86 -101,-799 -1142.27,-306.86 -1118.27,-306.86 410,81 427,81 1292.73,324.58 991.73,325.14 1132.73,326.14 991.73,344.14
  other v2: -50.13,-1253.72 149.73,-1144.48 928.23,-1040.86 950.73,-1040.86 905.73,-1019.86 929.23,-1019.86 952.73,-1019.86 898,-998
  other v4: 1132.73,345.14
DCDC6: C14.2 C15.1 C33.2 C34.2 C35.2 C36.2 C69.2 L7.2 U1.J14 U1.J16 U1.K13 U1.K16 U1.P13 U28.E12 | length 875.9
  TOP w5.5: 713,-827 713,-743
  TOP w6: U28.E12@649.04,-702.6 660.44,-714 684,-714 713,-743 ; 713,-827 L7.2@793.78,-907.77
  TOP w10: U1.P13@102.36,-332.68 v1(115.16,-345.48) ; U1.K13@102.36,-230.32 U1.J14@127.95,-204.73 140.75,-191.93 v1(166.34,-217.52) U1.J16@179.13,-204.73 ; 153.54,-204.73 166.33,-191.93 U1.J16@179.13,-204.73 ; U1.K16@179.13,-230.32 v1(191.93,-217.52) U1.J16@179.13,-204.73 ; v1(191.93,-191.93) U1.J16@179.13,-204.73 ; L7.2@793.78,-960.42 L7.2@793.78,-907.77
  SIN04 w10: v1(115.16,-345.48) 174,-286.64 174,-230.27 v1@167.73,-224
  BOTTOM w6: C15.1@118,-197.14 140.86,-197.14 C33.2@163,-175
  BOTTOM w10: v1(115.16,-345.48) 115.16,-346.16 C35.2@137,-368 ; 140.75,-191.93 157.68,-175 C33.2@163,-175 ; v1(191.93,-217.52) 202,-227.6 C34.2@202,-244 ; v1(191.93,-191.93) 214,-169.86 C36.2@214,-168
  other v2: 740.73,-994.86 759.23,-994.86 777.73,-994.86 759.73,-963.86 777.73,-963.86
  other v5: 741.73,-963.86
DCIN: C265.2 R463.1 U28.N15 U28.N16 | length 36.2
  TOP w5: v3(533.89,-485.08) U28.N16@546.68,-497.87 ; v3(559.48,-485.08) U28.N15@572.27,-497.87
  other v1: 411.73,-319 411.73,-301 429.73,-301
DLDO1: C229.2 C238.2 C239.1 C279.1 R173.1 R174.1 R176.1 R177.1 R178.1 R179.1 R180.1 R181.1 R182.1 R188.2 R190.2 R191.2 R192.2 U24.22 U28.F7 U28.J2 | length 4607.7
  TOP w5: 917.75,-587.44 943.33,-587.44
  TOP w8: U28.J2@904.95,-600.24 917.75,-587.44 ; 943.33,-587.44 v3(968.93,-561.85)
  TOP w12: U28.F7@777,-677.01 v3(789.8,-689.81)
  TOP w15: U24.22@-671.55,-723.52 -669.27,-721.24 v2(-669.27,-675.86)
  SIN03 w15: v2(-917.27,-1092.86) -917.27,-1181.27 -955,-1219 -955,-1266 -926,-1295 -797,-1295 -711,-1209 -562,-1209 -547,-1224 -422,-1224 -403,-1243 -314,-1243 -281,-1210 -248,-1210 -200.5,-1257.5 -160.5,-1257.5 -136,-1282 -46,-1282 -32,-1268 -9,-1268 41,-1318 104,-1318 140,-1282 195,-1282 282,-1195 282,-1140 v1(298,-1124) ; v3(789.8,-689.81) 789.8,-664.2 813.37,-640.63 857.37,-640.63 886,-612 899,-612 928,-583 959,-583 968.93,-573.07 v3(968.93,-561.85)
  SIN04 w15: v2(-888.27,-734.86) -877.13,-746 -853,-746 -825.29,-718.29 -711.71,-718.29 v2(-669.27,-675.86) ; v1(298,-1124) 339,-1124 346,-1117 463,-1117 494,-1148 703,-1148 773,-1078 773,-1038 799,-1012 799,-921 766,-888 766,-851 778,-839 778,-730 789.8,-718.2 v3(789.8,-689.81)
  BOTTOM w15: R190.2@-1033.89,-755.86 v2(-1033.89,-786.24) -1033.89,-835 ; R179.1@-1001.89,-892.11 -1033.89,-860.11 -1033.89,-835 ; -1001.89,-885.11 R180.1@-1001.89,-936.7 ; R182.1@-998.89,-1004.86 R182.1@-1001.89,-1007.86 R181.1@-1001.89,-972.28 R180.1@-1001.89,-936.7 ; v2(-917.27,-1092.86) R178.1@-888.65,-1092.86 ; R173.1@-888.65,-902.86 R174.1@-888.65,-940.86 -939,-940.86 ; v2(-888.27,-734.86) -888.27,-748.27 -947.24,-807.24 R192.2@-957.27,-807.24 -957.27,-812.27 -980.86,-835.86 -1033.04,-835.86 -1033.89,-835 ; C238.2@-887.1,-1130.86 -887.1,-1094.41 R178.1@-888.65,-1092.86 ; v2(-669.27,-675.86) -669.27,-704.73 -617,-757 -617,-860 -647.27,-890.27 R191.2@-647.27,-1002.48 ; v3(789.8,-689.81) 789.8,-663.85 C279.1@794.41,-659.24 ; v3(968.93,-561.85) 968.93,-590.48 C229.2@975.3,-596.86 ; R180.1@-1001.89,-936.7 -991.2,-926 -953.86,-926 -939,-940.86 ; -939,-940.86 -939,-998 -920.14,-1016.86 R176.1@-888.65,-1016.86 R177.1@-888.65,-1054.86 R178.1@-888.65,-1092.86
DLDO2: C75.1 U28.F8 | length 48.9
  TOP w12: U28.F8@751.41,-677.01 v3(764.21,-689.81)
  BOTTOM w5: C75.1@738.73,-676.86 C75.1@751.26,-676.86
  BOTTOM w15: C75.1@751.26,-676.86 v3(764.21,-689.81)
DLDO3: C77.1 U28.F10 | length 71.2
  TOP w12: v3(687.44,-689.81) U28.F10@700.23,-677.01
  BOTTOM w5: C77.1@648.41,-723.74 C77.1@653.5,-723.74
  BOTTOM w12: C77.1@653.5,-723.74 v3(687.44,-689.81)
DVDD-CSI-F: C271.1 U28.E16 | length 73.2
  TOP w5: v3(533.89,-715.4) U28.E16@546.68,-702.6
  BOTTOM w12: C271.1@491.2,-745.31 521.12,-715.4 v3(533.89,-715.4)
DVP_PWR: R4500.1 U1.D12 U14.3 U4500.3 U4502.3 | length 1870.6
  TOP w5: R4500.1@1161.73,302.14 1187.14,302.14 1194.73,309.73 v1@1194.73,341.14
  TOP w10: U1.D12@76.77,-76.78 v1(89.57,-63.98)
  SIN03 w4: v1(89.57,-63.98) 12.02,-63.98 8,-68 -31,-68 -53,-46 -53,-29 -29,-5 -29,76 32,137 253,137 269,153 427,153 436,144 649,144 v1(671,166)
  SIN04 w4: v1(671,166) 713,208 771,208 887.73,324.73 v1(887.73,344.14) ; v1@889.73,342.14 917.59,370 1018,370 1042.23,345.77 1042.23,340.14 1063.09,361 1174.87,361 v1@1194.73,341.14
  BOTTOM w10: v1@886.23,344.14 U14.3@886.23,377.14 ; v1@1040.73,341.64 U4500.3@1040.73,377.14 ; v1@1195.23,341.64 U4502.3@1195.23,377.14
  other v1: 1042.23,344.14 1194.73,344.14
ELDO1: C83.1 U28.G15 | length 148.7
  TOP w5: v3(559.48,-664.22) U28.G15@572.27,-651.42
  BOTTOM w12: C83.1@469.73,-586.24 499.73,-616.24 499.73,-630.86 514.87,-646 541.26,-646 v3(559.48,-664.22)
ELDO2: C278.1 U28.D16 | length 107.6
  TOP w5: v3(533.89,-740.98) U28.D16@546.68,-728.19
  BOTTOM w12: C278.1@490.41,-797.24 516.35,-797.24 533.89,-779.69 v3(533.89,-740.98)
ENTER: R134.2 R135.1 TP47.1 | length 97.1
  BOTTOM w5: TP47.1@1254.73,-573.86 1260.11,-568.48 R135.1@1260.11,-514.86 R134.2@1295.97,-514.86
FLDO1: C89.2 U1.P14 U28.E15 | length 854.3
  TOP w5: v3(559.48,-715.4) U28.E15@572.27,-702.6
  TOP w10: U1.P14@127.95,-332.68 v1(140.75,-345.48)
  SIN03 w10: v1(140.75,-345.48) 157.27,-362 175,-362 184,-353 231,-353 264,-386 336,-386 403.53,-453.53 403.53,-474.47 385,-493 385,-540.92 v3(559.48,-715.4)
  BOTTOM w12: C89.2@494.73,-849.86 552.73,-791.86 552.73,-722.15 v3(559.48,-715.4)
FLDO2: C17.2 C18.2 C90.2 U1.R17 U1.T17 U28.F14 | length 1003.8
  TOP w10: U1.T17@204.72,-383.86 v1(217.52,-371.06) U1.R17@204.72,-358.27 ; v3(585.07,-689.81) U28.F14@597.86,-677.01
  SIN03 w10: v1(217.52,-371.06) 217.52,-394.52 237,-414 342,-414 362,-434 362,-539 487,-664 487,-720 525,-758 542,-758 585.07,-714.93 v3(585.07,-689.81)
  BOTTOM w8: v1(217.52,-371.06) 259.06,-371.06 C17.2@274,-386
  BOTTOM w10: v1(217.52,-371.06) 235.72,-352.86 C18.2@235.72,-345 ; C90.2@546.41,-847.74 C90.2@555.01,-839.14 ; C90.2@553.73,-837.86 555.73,-837.86 574.73,-818.86 574.73,-726.86 585.07,-716.52 v3(585.07,-689.81)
